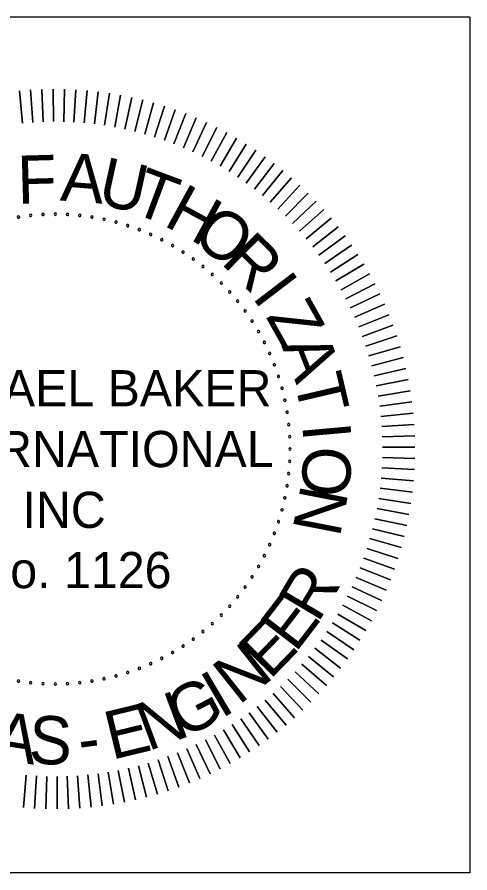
# Model space of a CAD drawing. Extents: x -549 to 3324, y -742 to 2142.
# Drawn here: x 2866.5 to 3023.2, y 78.3 to 374.1 of the extents above; entities that cross this region are included whole.
import ezdxf

# ---------------------------------------------------------------- set-up
doc = ezdxf.new("R2010")
doc.units = 0
doc.layers.add('G-ANNO-TEXT', color=7, linetype='Continuous')
doc.layers.add('R_No Plot', color=7, linetype='Continuous')

msp = doc.modelspace()

# ---------------------------------------------------------------- linework, layer by layer
at = {"layer": 'G-ANNO-TEXT'}
for points in [[(2875.51, 337.96), (2875.1, 349.17)], [(2875.1, 349.17), (2875.51, 337.96)], [(2879.07, 338.04), (2879.01, 349.26)], [(2879.01, 349.26), (2879.07, 338.04)], [(2882.63, 338), (2882.92, 349.22)], [(2882.92, 349.22), (2882.63, 338)], [(2868.42, 337.47), (2867.3, 348.64)], [(2867.3, 348.64), (2868.42, 337.47)], [(2871.96, 337.77), (2871.19, 348.97)], [(2871.19, 348.97), (2871.96, 337.77)], [(2886.18, 337.85), (2886.82, 349.06)], [(2886.82, 349.06), (2886.18, 337.85)], [(2889.73, 337.59), (2890.72, 348.77)], [(2890.72, 348.77), (2889.73, 337.59)], [(2893.26, 337.22), (2894.61, 348.36)], [(2894.61, 348.36), (2893.26, 337.22)], [(2896.79, 336.74), (2898.48, 347.83)], [(2898.48, 347.83), (2896.79, 336.74)], [(2900.3, 336.15), (2902.34, 347.18)], [(2902.34, 347.18), (2900.3, 336.15)], [(2903.78, 335.45), (2906.17, 346.41)], [(2906.17, 346.41), (2903.78, 335.45)], [(2907.25, 334.64), (2909.98, 345.52)], [(2909.98, 345.52), (2907.25, 334.64)], [(2910.68, 333.72), (2913.75, 344.51)], [(2913.75, 344.51), (2910.68, 333.72)], [(2914.09, 332.69), (2917.49, 343.38)], [(2917.49, 343.38), (2914.09, 332.69)], [(2917.46, 331.56), (2921.2, 342.14)], [(2921.2, 342.14), (2917.46, 331.56)], [(2920.79, 330.32), (2924.86, 340.77)], [(2924.86, 340.77), (2920.79, 330.32)], [(2924.09, 328.97), (2928.48, 339.3)], [(2928.48, 339.3), (2924.09, 328.97)], [(2927.33, 327.53), (2932.06, 337.71)], [(2932.06, 337.71), (2927.33, 327.53)], [(2930.54, 325.98), (2935.58, 336.01)], [(2935.58, 336.01), (2930.54, 325.98)], [(2933.69, 324.34), (2939.04, 334.2)], [(2939.04, 334.2), (2933.69, 324.34)], [(2936.79, 322.59), (2942.45, 332.28)], [(2942.45, 332.28), (2936.79, 322.59)], [(2939.83, 320.75), (2945.79, 330.26)], [(2945.79, 330.26), (2939.83, 320.75)], [(2942.82, 318.81), (2949.07, 328.13)], [(2949.07, 328.13), (2942.82, 318.81)], [(2945.74, 316.78), (2952.28, 325.9)], [(2952.28, 325.9), (2945.74, 316.78)], [(2948.59, 314.66), (2955.42, 323.57)], [(2955.42, 323.57), (2948.59, 314.66)], [(2951.38, 312.46), (2958.49, 321.14)], [(2958.49, 321.14), (2951.38, 312.46)], [(2954.1, 310.16), (2961.47, 318.62)], [(2961.47, 318.62), (2954.1, 310.16)], [(2964.38, 316.01), (2956.74, 307.78)], [(2956.74, 307.78), (2964.38, 316.01)], [(2967.2, 313.3), (2959.31, 305.32)], [(2959.31, 305.32), (2967.2, 313.3)], [(2969.94, 310.51), (2961.8, 302.78)], [(2961.8, 302.78), (2969.94, 310.51)], [(2972.58, 307.63), (2964.21, 300.16)], [(2964.21, 300.16), (2972.58, 307.63)], [(2975.14, 304.67), (2966.53, 297.47)], [(2966.53, 297.47), (2975.14, 304.67)], [(2977.6, 301.64), (2968.77, 294.71)], [(2968.77, 294.71), (2977.6, 301.64)], [(2979.97, 298.52), (2970.92, 291.88)], [(2970.92, 291.88), (2979.97, 298.52)], [(2982.23, 295.34), (2972.99, 288.98)], [(2972.99, 288.98), (2982.23, 295.34)], [(2984.4, 292.08), (2974.95, 286.02)], [(2974.95, 286.02), (2984.4, 292.08)], [(2986.46, 288.76), (2976.83, 282.99)], [(2976.83, 282.99), (2986.46, 288.76)], [(2988.41, 285.38), (2978.61, 279.91)], [(2978.61, 279.91), (2988.41, 285.38)], [(2990.26, 281.93), (2980.29, 276.78)], [(2980.29, 276.78), (2990.26, 281.93)], [(2992, 278.43), (2981.87, 273.59)], [(2981.87, 273.59), (2992, 278.43)], [(2993.63, 274.88), (2983.36, 270.36)], [(2983.36, 270.36), (2993.63, 274.88)], [(2995.15, 271.27), (2984.73, 267.08)], [(2984.73, 267.08), (2995.15, 271.27)], [(2996.55, 267.62), (2986.01, 263.76)], [(2986.01, 263.76), (2996.55, 267.62)], [(2997.83, 263.93), (2987.18, 260.4)], [(2987.18, 260.4), (2997.83, 263.93)], [(2999.01, 260.2), (2988.25, 257.01)], [(2988.25, 257.01), (2999.01, 260.2)], [(3000.06, 256.44), (2989.2, 253.59)], [(2989.2, 253.59), (3000.06, 256.44)], [(3000.99, 252.64), (2990.05, 250.13)], [(2990.05, 250.13), (3000.99, 252.64)], [(3001.81, 248.82), (2990.79, 246.65)], [(2990.79, 246.65), (3001.81, 248.82)], [(3002.5, 244.97), (2991.42, 243.15)], [(2991.42, 243.15), (3002.5, 244.97)], [(3003.07, 241.1), (2991.95, 239.63)], [(2991.95, 239.63), (3003.07, 241.1)], [(3003.52, 237.22), (2992.36, 236.1)], [(2992.36, 236.1), (3003.52, 237.22)], [(3003.85, 233.32), (2992.65, 232.56)], [(2992.65, 232.56), (3003.85, 233.32)], [(3004.06, 229.42), (2992.84, 229.01)], [(2992.84, 229.01), (3004.06, 229.42)], [(3004.14, 225.51), (2992.92, 225.45)], [(2992.92, 225.45), (3004.14, 225.51)], [(3004.1, 221.6), (2992.88, 221.89)], [(2992.88, 221.89), (3004.1, 221.6)], [(3003.94, 217.7), (2992.73, 218.34)], [(2992.73, 218.34), (3003.94, 217.7)], [(3003.65, 213.8), (2992.47, 214.79)], [(2992.47, 214.79), (3003.65, 213.8)], [(3003.25, 209.91), (2992.1, 211.25)], [(2992.1, 211.25), (3003.25, 209.91)], [(3002.72, 206.04), (2991.62, 207.73)], [(2991.62, 207.73), (3002.72, 206.04)], [(3002.07, 202.18), (2991.03, 204.22)], [(2991.03, 204.22), (3002.07, 202.18)], [(3001.29, 198.35), (2990.33, 200.74)], [(2990.33, 200.74), (3001.29, 198.35)], [(3000.4, 194.54), (2989.52, 197.27)], [(2989.52, 197.27), (3000.4, 194.54)], [(2999.39, 190.77), (2988.6, 193.84)], [(2988.6, 193.84), (2999.39, 190.77)], [(2998.26, 187.02), (2987.57, 190.43)], [(2987.57, 190.43), (2998.26, 187.02)], [(2997.02, 183.32), (2986.44, 187.06)], [(2986.44, 187.06), (2997.02, 183.32)], [(2995.66, 179.65), (2985.2, 183.73)], [(2985.2, 183.73), (2995.66, 179.65)], [(2994.18, 176.03), (2983.86, 180.43)], [(2983.86, 180.43), (2994.18, 176.03)], [(2992.59, 172.46), (2982.41, 177.18)], [(2982.41, 177.18), (2992.59, 172.46)], [(2990.89, 168.94), (2980.86, 173.98)], [(2980.86, 173.98), (2990.89, 168.94)], [(2989.08, 165.48), (2979.22, 170.83)], [(2979.22, 170.83), (2989.08, 165.48)], [(2987.16, 162.07), (2977.47, 167.73)], [(2977.47, 167.73), (2987.16, 162.07)], [(2985.14, 158.73), (2975.63, 164.69)], [(2975.63, 164.69), (2985.14, 158.73)], [(2983.01, 155.45), (2973.69, 161.7)], [(2973.69, 161.7), (2983.01, 155.45)], [(2980.78, 152.24), (2971.67, 158.78)], [(2971.67, 158.78), (2980.78, 152.24)], [(2978.45, 149.1), (2969.55, 155.93)], [(2969.55, 155.93), (2978.45, 149.1)], [(2976.02, 146.03), (2967.34, 153.14)], [(2967.34, 153.14), (2976.02, 146.03)], [(2973.5, 143.05), (2965.04, 150.42)], [(2965.04, 150.42), (2973.5, 143.05)], [(2968.18, 137.32), (2960.2, 145.21)], [(2960.2, 145.21), (2968.18, 137.32)], [(2970.89, 140.14), (2962.66, 147.78)], [(2962.66, 147.78), (2970.89, 140.14)], [(2965.39, 134.58), (2957.66, 142.72)], [(2957.66, 142.72), (2965.39, 134.58)], [(2962.51, 131.93), (2955.05, 140.31)], [(2955.05, 140.31), (2962.51, 131.93)], [(2959.56, 129.38), (2952.35, 137.99)], [(2952.35, 137.99), (2959.56, 129.38)], [(2953.4, 124.55), (2946.76, 133.59)], [(2946.76, 133.59), (2953.4, 124.55)], [(2956.52, 126.92), (2949.59, 135.75)], [(2949.59, 135.75), (2956.52, 126.92)], [(2950.22, 122.29), (2943.86, 131.53)], [(2943.86, 131.53), (2950.22, 122.29)], [(2943.64, 118.06), (2937.88, 127.69)], [(2937.88, 127.69), (2943.64, 118.06)], [(2946.96, 120.12), (2940.9, 129.56)], [(2940.9, 129.56), (2946.96, 120.12)], [(2940.26, 116.11), (2934.8, 125.91)], [(2934.8, 125.91), (2940.26, 116.11)], [(2933.31, 112.52), (2928.48, 122.65)], [(2928.48, 122.65), (2933.31, 112.52)], [(2936.81, 114.26), (2931.66, 124.23)], [(2931.66, 124.23), (2936.81, 114.26)], [(2922.51, 107.97), (2918.64, 118.51)], [(2918.64, 118.51), (2922.51, 107.97)], [(2926.15, 109.37), (2921.96, 119.78)], [(2921.96, 119.78), (2926.15, 109.37)], [(2929.76, 110.89), (2925.24, 121.16)], [(2925.24, 121.16), (2929.76, 110.89)], [(2915.08, 105.51), (2911.89, 116.27)], [(2911.89, 116.27), (2915.08, 105.51)], [(2918.81, 106.68), (2915.29, 117.34)], [(2915.29, 117.34), (2918.81, 106.68)], [(2895.98, 101.45), (2894.52, 112.57)], [(2894.52, 112.57), (2895.98, 101.45)], [(2899.85, 102.02), (2898.03, 113.09)], [(2898.03, 113.09), (2899.85, 102.02)], [(2903.7, 102.71), (2901.53, 113.73)], [(2901.53, 113.73), (2903.7, 102.71)], [(2907.52, 103.53), (2905.01, 114.47)], [(2905.01, 114.47), (2907.52, 103.53)], [(2911.32, 104.46), (2908.47, 115.32)], [(2908.47, 115.32), (2911.32, 104.46)], [(2868.68, 100.87), (2869.67, 112.04)], [(2869.67, 112.04), (2868.68, 100.87)], [(2872.58, 100.58), (2873.22, 111.79)], [(2873.22, 111.79), (2872.58, 100.58)], [(2876.48, 100.42), (2876.77, 111.64)], [(2876.77, 111.64), (2876.48, 100.42)], [(2880.39, 100.38), (2880.33, 111.6)], [(2880.33, 111.6), (2880.39, 100.38)], [(2884.3, 100.46), (2883.89, 111.68)], [(2883.89, 111.68), (2884.3, 100.46)], [(2888.21, 100.67), (2887.44, 111.86)], [(2887.44, 111.86), (2888.21, 100.67)], [(2892.1, 101), (2890.98, 112.16)], [(2890.98, 112.16), (2892.1, 101)]]:
    msp.add_lwpolyline(points, dxfattribs=at)
for centre, start, end in [((2867, 305.03), 9, 189), ((2867, 305.03), 189, 9), ((2871.21, 305.59), 6, 186), ((2871.21, 305.59), 186, 6), ((2875.45, 305.92), 3, 183), ((2875.45, 305.92), 183, 3), ((2879.7, 306.03), 0, 180), ((2879.7, 306.03), 180, 0), ((2883.95, 305.92), 357, 177), ((2883.95, 305.92), 177, 357), ((2888.19, 305.59), 174, 354), ((2888.19, 305.59), 354, 174), ((2892.41, 305.03), 351, 171), ((2892.41, 305.03), 171, 351), ((2896.59, 304.26), 168, 348), ((2896.59, 304.26), 348, 168), ((2900.72, 303.27), 165, 345), ((2900.72, 303.27), 345, 165), ((2904.8, 302.06), 162, 342), ((2904.8, 302.06), 342, 162), ((2908.81, 300.64), 159, 339), ((2908.81, 300.64), 339, 159), ((2912.73, 299.01), 156, 336), ((2912.73, 299.01), 336, 156), ((2916.57, 297.18), 153, 333), ((2916.57, 297.18), 333, 153), ((2920.31, 295.15), 150, 330), ((2920.31, 295.15), 330, 150), ((2923.93, 292.93), 147, 327), ((2923.93, 292.93), 327, 147), ((2927.44, 290.52), 144, 324), ((2927.44, 290.52), 324, 144), ((2930.81, 287.93), 141, 321), ((2930.81, 287.93), 321, 141), ((2934.04, 285.17), 138, 318), ((2934.04, 285.17), 318, 138), ((2937.13, 282.25), 135, 315), ((2937.13, 282.25), 315, 135), ((2940.05, 279.16), 132, 312), ((2940.05, 279.16), 312, 132), ((2942.82, 275.93), 129, 309), ((2942.82, 275.93), 309, 129), ((2945.4, 272.56), 126, 306), ((2945.4, 272.56), 306, 126), ((2947.81, 269.05), 123, 303), ((2947.81, 269.05), 303, 123), ((2950.03, 265.43), 120, 300), ((2950.03, 265.43), 300, 120), ((2952.06, 261.69), 117, 297), ((2952.06, 261.69), 297, 117), ((2953.89, 257.85), 114, 294), ((2953.89, 257.85), 294, 114), ((2955.52, 253.92), 111, 291), ((2955.52, 253.92), 291, 111), ((2956.94, 249.92), 108, 288), ((2956.94, 249.92), 288, 108), ((2958.15, 245.84), 105, 285), ((2958.15, 245.84), 285, 105), ((2959.14, 241.7), 102, 282), ((2959.14, 241.7), 282, 102), ((2959.92, 237.52), 99, 279), ((2959.92, 237.52), 279, 99), ((2960.47, 233.31), 96, 276), ((2960.47, 233.31), 276, 96), ((2960.8, 229.07), 93, 273), ((2960.8, 229.07), 273, 93), ((2960.91, 224.82), 90, 270), ((2960.91, 224.82), 270, 90), ((2960.8, 220.57), 87, 267), ((2960.8, 220.57), 267, 87), ((2960.47, 216.33), 84, 264), ((2960.47, 216.33), 264, 84), ((2959.92, 212.11), 81, 261), ((2959.92, 212.11), 261, 81), ((2959.14, 207.93), 78, 258), ((2959.14, 207.93), 258, 78), ((2958.15, 203.8), 75, 255), ((2958.15, 203.8), 255, 75), ((2956.94, 199.72), 72, 252), ((2956.94, 199.72), 252, 72), ((2955.52, 195.71), 69, 249), ((2955.52, 195.71), 249, 69), ((2953.89, 191.79), 66, 246), ((2953.89, 191.79), 246, 66), ((2952.06, 187.95), 63, 243), ((2952.06, 187.95), 243, 63), ((2950.03, 184.21), 60, 240), ((2950.03, 184.21), 240, 60), ((2947.81, 180.59), 57, 237), ((2947.81, 180.59), 237, 57), ((2945.4, 177.08), 54, 234), ((2945.4, 177.08), 234, 54), ((2942.82, 173.71), 51, 231), ((2942.82, 173.71), 231, 51), ((2940.05, 170.48), 48, 228), ((2940.05, 170.48), 228, 48), ((2937.13, 167.39), 45, 225), ((2937.13, 167.39), 225, 45), ((2934.04, 164.46), 42, 222), ((2934.04, 164.46), 222, 42), ((2930.81, 161.7), 39, 219), ((2930.81, 161.7), 219, 39), ((2923.93, 156.71), 33, 213), ((2923.93, 156.71), 213, 33), ((2927.44, 159.11), 36, 216), ((2927.44, 159.11), 216, 36), ((2920.31, 154.48), 30, 210), ((2920.31, 154.48), 210, 30), ((2912.73, 150.63), 24, 204), ((2916.57, 152.46), 27, 207), ((2916.57, 152.46), 207, 27), ((2904.8, 147.58), 18, 198), ((2908.81, 149), 21, 201), ((2908.81, 149), 201, 21), ((2912.73, 150.63), 204, 24), ((2867, 144.6), 351, 171), ((2892.41, 144.6), 9, 189), ((2896.59, 145.38), 12, 192), ((2896.59, 145.38), 192, 12), ((2900.72, 146.37), 15, 195), ((2900.72, 146.37), 195, 15), ((2904.8, 147.58), 198, 18), ((2867, 144.6), 171, 351), ((2871.21, 144.05), 174, 354), ((2871.21, 144.05), 354, 174), ((2875.45, 143.72), 357, 177), ((2875.45, 143.72), 177, 357), ((2879.7, 143.6), 0, 180), ((2879.7, 143.6), 180, 0), ((2883.95, 143.72), 3, 183), ((2883.95, 143.72), 183, 3), ((2888.19, 144.05), 6, 186), ((2888.19, 144.05), 186, 6), ((2892.41, 144.6), 189, 9)]:
    msp.add_arc(centre, 0.417, start, end, dxfattribs=at)
at = {"layer": 'R_No Plot'}
for p, q in [((3023.16, 374.15), (2727.29, 374.15)), ((3023.16, 374.15), (3023.16, 78.28)), ((3023.16, 78.28), (2727.29, 78.28))]:
    msp.add_line(p, q, dxfattribs=at)

# ---------------------------------------------------------------- texts
at = {"layer": 'G-ANNO-TEXT'}
for s, rotation, p in [('F', 1.5867, (2866.77, 309.55)), ('A', 355.5955, (2881.22, 310.77)), ('U', 347.5481, (2893.83, 309.59)), ('T', 339.5007, (2905.47, 306.81)), ('H', 331.4533, (2916.77, 302.35)), ('O', 323.4059, (2926.34, 297.08)), ('R', 315.3585, (2936.67, 289.18)), ('I', 307.3112, (2947.5, 277.44)), ('Z', 299.2638, (2952.4, 270.64)), ('A', 291.2164, (2957.86, 260.62)), ('T', 283.169, (2962.22, 248.83)), ('I', 275.1216, (2965.11, 233.23)), ('O', 267.0743, (2965.69, 226.06)), ('N', 259.0269, (2964.82, 212.96)), ('R', 59.2262, (2970.57, 164.38)), ('E', 52.4765, (2962.83, 154.12)), ('E', 45.7268, (2953.95, 144.84)), ('N', 38.4196, (2943.17, 136.04)), ('I', 30.5495, (2937.12, 131.45)), ('G', 27.7404, (2923.94, 124.46)), ('N', 20.4332, (2911.81, 120.25)), ('E', 13.6835, (2899.25, 117.31)), ('A', 351.1991, (2857.65, 117.94)), ('S', 357.9489, (2870.36, 116.09)), ('-', 7.5077, (2888.55, 116.05))]:
    msp.add_text(s, height=16.67, rotation=rotation, dxfattribs=at).set_placement(p)
for s, height, p in [('MICHAEL BAKER', 12.5016, (2818.87, 239.59)), (' INTERNATIONAL', 12.5016, (2816.86, 218.57)), ('INC', 12.502, (2868.38, 197.55)), (' No. 1126', 12.502, (2847.43, 176.72))]:
    msp.add_text(s, height=height, dxfattribs=at).set_placement(p)

doc.saveas('drawing.dxf')
